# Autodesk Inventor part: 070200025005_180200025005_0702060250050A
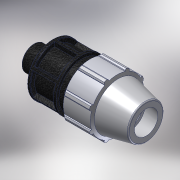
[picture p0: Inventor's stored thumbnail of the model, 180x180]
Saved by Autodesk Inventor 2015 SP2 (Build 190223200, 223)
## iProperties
Created: 2017-02
Part Number: 070200025005_180200025005_0702060250050A
Material: PVC-Piping
Description: PLASSON MALE ADAPTOR 25-1/2"
Document SubType Name: Modeling
Designer: KIM
Mass: 92.6774 g
Surface Area: 199.44 cm^2
Volume: 66.1981 cm^3
Density: 1.4 g/cm^3
Appearance: PTFE
Author: KIM
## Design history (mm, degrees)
derived "07020.ipt"
feature "Solid1::07020.ipt"
tag "TaggingFeature1"
body "Solid1"
other parameters: "d2" = 25, "d4" = 13.42857, "d5" = 23.5, "d7" = 54, "d8" = 40.5, "d9" = 13.42857, "d11" = 2.68571, "d12" = 43.2, "d13" = 120 deg, "d14" = 37.5, "d15" = 12 deg, "d16" = 48.6, "d18" = 1.25, "d19" = 35 deg, "d20" = 17.5 deg, "d21" = 50.22, "d23" = 0, "d25" = 360 deg, "d27" = 1.08, "d34" = 2.7, "d36" = 0, "d42" = 23.5, "d43" = 1.62, "d46" = 0.75, "d49" = 72, "d51" = 94, "d52" = 17, "d53" = 0.5, "d55" = 360 deg, "d57" = 20.955, "d58" = 14.6685, "d59" = 18.8, "d_" = 25, "E_" = 54, "H_" = 94, "l_" = 72, "l_2" = 17, "R_" = 20.955
